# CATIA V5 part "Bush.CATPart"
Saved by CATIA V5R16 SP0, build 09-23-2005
Part number: Bush
Bounding box of the stored display mesh (mm): x -19.994 to 19.994, y 0 to 18, z -19.994 to 19.994
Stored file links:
  C:\V5_education\CATIA Data\ASD\Power Transmission Gear Assembly\Assembly Data\Bush.CATPart
  C:\V5_education\CATIA Data\ASD\Power Transmission Gear Assembly\Assembly Data\Power Transmission Gear Assembly.CATProduct
  C:\V5_education\CATIA Data\ASD\Power Transmission Gear Assembly\Assembly Data\Power Transmission Gear.CATPart
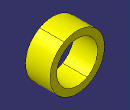
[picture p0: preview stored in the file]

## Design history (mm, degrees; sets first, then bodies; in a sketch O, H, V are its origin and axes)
Set1
  DatumSurface1: linked copy from another document
Set2 "Reference Data"
  Point1 "Center Point": (0, 0, 0)
Body1 (main body)
  Sketch1 on yz-plane, origin (0, 0, 0), H (0, 1, 0), V (0, 0, 1)
    axis line L1 (0, 0) -> (70.7713, 0)
    line L2 (0, 15) -> (0, 20)
    line L3 (0, 20) -> (18, 20)
    line L4 (18, 20) -> (18, 15)
    line L5 (0, 15) -> (18, 15)
    distance L5 L1 = 15
    distance L3 L1 = 20
    distance L2 L4 = 18
    horizontal: L1 H, L3 H, L5 H
    vertical: L2 V, L4 V
    coincidence: O L2
  Shaft1: profile Sketch1, axis Sketch1.L1, angle 360
  AssyPrtSPLIT1: SplitPlane DatumSurface1, _MechModInactiveResultOUT result of AssyPrtSPLIT1, deactivated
